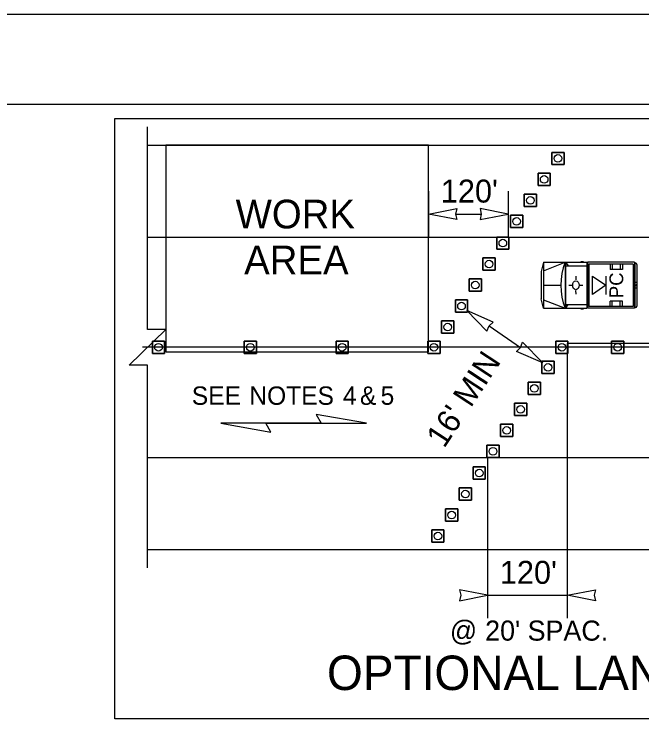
# Model space of a CAD drawing. Extents: x 99999.1 to 100095.7, y 99995 to 100010.7.
# Drawn here: x 100005.12 to 100007.305, y 100008.165 to 100010.687 of the extents above; entities that cross this region are included whole.
import ezdxf

# ---------------------------------------------------------------- set-up
doc = ezdxf.new("R2010")
doc.units = 0
for name, color, linetype in [('RD_ED_ShoulderPavedEdge', 7, 'Continuous'), ('RD_MK_LineEdgeWhite', 7, 'Continuous'), ('RD_MK_LineSkipCenter', 7, 'Continuous'), ('SH_DE_DetailHeading2Text', 7, 'Continuous'), ('SH_GI_PlotLimits', 7, 'Continuous'), ('SH_GI_SheetBorder', 7, 'Continuous'), ('SH_TI_Tables', 7, 'Continuous'), ('TR_WZ_MotoristVehicle', 7, 'Continuous'), ('TR_WZ_PortableSignMountBlk-Wht', 7, 'Continuous'), ('TR_WZ_TrafficCone', 7, 'Continuous'), ('TR_WZ_WorkAreaLabel', 7, 'Continuous'), ('TR_WZ_WorkZoneDetails', 7, 'Continuous'), ('TR_WZ_WorkZoneTextCurrent', 7, 'Continuous')]:
    doc.layers.add(name, color=color, linetype=linetype)

msp = doc.modelspace()

# ---------------------------------------------------------------- linework, layer by layer
at = {"layer": 'RD_ED_ShoulderPavedEdge'}
for p, q in [((100005.5832, 100010.2323), (100009.5005, 100010.2323)), ((100005.5832, 100008.8243), (100009.5005, 100008.8243))]:
    msp.add_line(p, q, dxfattribs=at)
at = {"layer": 'RD_MK_LineEdgeWhite'}
for p, q in [((100005.5832, 100009.9123), (100009.5005, 100009.9123)), ((100005.5832, 100009.1443), (100009.5005, 100009.1443))]:
    msp.add_line(p, q, dxfattribs=at)
at = {"layer": 'RD_MK_LineSkipCenter'}
msp.add_lwpolyline([(100009.484, 100009.5283), (100005.5667, 100009.5283)], dxfattribs=at)
at = {"layer": 'SH_GI_PlotLimits'}
msp.add_lwpolyline([(99999.0625, 99999.6875), (100016.0625, 99999.6875), (100016.0625, 100010.6875), (99999.0625, 100010.6875)], close=True, dxfattribs=at)
at = {"layer": 'SH_GI_SheetBorder'}
msp.add_line((100000, 100010.375), (100015.75, 100010.375), dxfattribs=at)
at = {"layer": 'SH_TI_Tables'}
msp.add_lwpolyline([(100005.4692, 100010.325), (100009.6146, 100010.325), (100009.6146, 100008.2343), (100005.4692, 100008.2343)], close=True, dxfattribs=at)
at = {"layer": 'TR_WZ_MotoristVehicle'}
for p, q in [((100006.9633, 100009.8243), (100006.9559, 100009.792)), ((100006.9633, 100009.8243), (100006.9633, 100009.6643)), ((100006.9633, 100009.8243), (100007.1144, 100009.8243)), ((100006.9633, 100009.795), (100007.0388, 100009.8243)), ((100007.0388, 100009.8243), (100007.0388, 100009.6643)), ((100007.0402, 100009.8243), (100007.0402, 100009.6643)), ((100007.0402, 100009.8243), (100007.0498, 100009.8119)), ((100007.0402, 100009.8119), (100007.1144, 100009.8119)), ((100007.0938, 100009.8266), (100007.1029, 100009.8266)), ((100007.1144, 100009.8243), (100007.1144, 100009.6643)), ((100007.2812, 100009.8243), (100007.1166, 100009.8243)), ((100007.1166, 100009.8243), (100007.1166, 100009.6643)), ((100007.2765, 100009.8179), (100007.1213, 100009.8179)), ((100007.1213, 100009.8179), (100007.1213, 100009.6707)), ((100007.1955, 100009.8179), (100007.1955, 100009.7995)), ((100007.2034, 100009.8179), (100007.2034, 100009.7995)), ((100007.2306, 100009.8179), (100007.2306, 100009.7995)), ((100007.2394, 100009.8179), (100007.2394, 100009.7995)), ((100007.2765, 100009.8179), (100007.2765, 100009.6707)), ((100007.2812, 100009.8243), (100007.2812, 100009.6643)), ((100007.2853, 100009.8217), (100007.2817, 100009.8217)), ((100007.2817, 100009.8217), (100007.2817, 100009.667)), ((100007.2889, 100009.8168), (100007.2889, 100009.6718)), ((100006.9559, 100009.792), (100006.9559, 100009.6966)), ((100007.2394, 100009.7995), (100007.1955, 100009.7995)), ((100007.0765, 100009.776), (100007.0765, 100009.7631)), ((100006.9633, 100009.7443), (100007.024, 100009.7443)), ((100007.0524, 100009.7444), (100007.0624, 100009.7444)), ((100007.0877, 100009.7441), (100007.0877, 100009.7441)), ((100007.1012, 100009.7437), (100007.0893, 100009.744)), ((100007.2889, 100009.7556), (100007.2817, 100009.7526)), ((100007.2889, 100009.7331), (100007.2817, 100009.7361)), ((100007.2869, 100009.7443), (100007.2837, 100009.7443)), ((100007.2853, 100009.7466), (100007.2853, 100009.7421)), ((100007.077, 100009.7136), (100007.0768, 100009.7256)), ((100006.9633, 100009.6643), (100006.9559, 100009.6966)), ((100006.9633, 100009.6936), (100007.0388, 100009.6643)), ((100007.1955, 100009.6707), (100007.1955, 100009.6891)), ((100007.2394, 100009.6891), (100007.1955, 100009.6891)), ((100007.2034, 100009.6707), (100007.2034, 100009.6891)), ((100007.2306, 100009.6707), (100007.2306, 100009.6891)), ((100007.2394, 100009.6707), (100007.2394, 100009.6891)), ((100006.9633, 100009.6643), (100007.1144, 100009.6643)), ((100007.0402, 100009.6767), (100007.1144, 100009.6767)), ((100007.0482, 100009.6767), (100007.0402, 100009.6643)), ((100007.0938, 100009.6621), (100007.1029, 100009.6621)), ((100007.2812, 100009.6643), (100007.1166, 100009.6643)), ((100007.2765, 100009.6707), (100007.1213, 100009.6707)), ((100007.2853, 100009.667), (100007.2817, 100009.667))]:
    msp.add_line(p, q, dxfattribs=at)
for centre, major_axis, start_param, end_param in [((100007.1468, 100009.7443), (0, -0.1679), 4.215667, 5.208926), ((100007.2853, 100009.8168), (0, 0.00488), 4.712389, 6.283185), ((100007.2853, 100009.6718), (0, -0.00488), 0, 1.570796)]:
    msp.add_ellipse(centre, major_axis=major_axis, ratio=0.73155, start_param=start_param, end_param=end_param, dxfattribs=at)
for centre, major_axis in [((100007.0765, 100009.7443), (0, 0.0154)), ((100007.2853, 100009.7443), (0, 0.00225))]:
    msp.add_ellipse(centre, major_axis=major_axis, ratio=0.73155, dxfattribs=at)
at = {"layer": 'TR_WZ_PortableSignMountBlk-Wht'}
msp.add_line((100007.1803, 100009.7763), (100007.1803, 100009.7123), dxfattribs=at)
msp.add_lwpolyline([(100007.1803, 100009.7443), (100007.1344, 100009.7123), (100007.1344, 100009.7763)], close=True, dxfattribs=at)
at = {"layer": 'TR_WZ_TrafficCone'}
for points in [[(100006.9925, 100010.2073), (100007.0352, 100010.2073), (100007.0352, 100010.1646), (100006.9925, 100010.1646), (100006.9925, 100010.2073)], [(100006.9925, 100010.1646), (100007.0352, 100010.1646), (100007.0352, 100010.2073), (100006.9925, 100010.2073), (100006.9925, 100010.1646)], [(100006.9445, 100010.1342), (100006.9872, 100010.1342), (100006.9872, 100010.0915), (100006.9445, 100010.0915), (100006.9445, 100010.1342)], [(100006.9445, 100010.0915), (100006.9872, 100010.0915), (100006.9872, 100010.1342), (100006.9445, 100010.1342), (100006.9445, 100010.0915)], [(100006.8965, 100010.0611), (100006.9392, 100010.0611), (100006.9392, 100010.0185), (100006.8965, 100010.0185), (100006.8965, 100010.0611)], [(100006.8965, 100010.0185), (100006.9392, 100010.0185), (100006.9392, 100010.0611), (100006.8965, 100010.0611), (100006.8965, 100010.0185)], [(100006.8485, 100009.9881), (100006.8912, 100009.9881), (100006.8912, 100009.9454), (100006.8485, 100009.9454), (100006.8485, 100009.9881)], [(100006.8485, 100009.9454), (100006.8912, 100009.9454), (100006.8912, 100009.9881), (100006.8485, 100009.9881), (100006.8485, 100009.9454)], [(100006.8432, 100009.9123), (100006.8005, 100009.9123), (100006.8005, 100009.8697), (100006.8432, 100009.8697), (100006.8432, 100009.9123)], [(100006.8432, 100009.8697), (100006.8005, 100009.8697), (100006.8005, 100009.9123), (100006.8432, 100009.9123), (100006.8432, 100009.8697)], [(100006.7952, 100009.8393), (100006.7525, 100009.8393), (100006.7525, 100009.7966), (100006.7952, 100009.7966), (100006.7952, 100009.8393)], [(100006.7952, 100009.7966), (100006.7525, 100009.7966), (100006.7525, 100009.8393), (100006.7952, 100009.8393), (100006.7952, 100009.7966)], [(100006.7472, 100009.7662), (100006.7045, 100009.7662), (100006.7045, 100009.7235), (100006.7472, 100009.7235), (100006.7472, 100009.7662)], [(100006.7472, 100009.7235), (100006.7045, 100009.7235), (100006.7045, 100009.7662), (100006.7472, 100009.7662), (100006.7472, 100009.7235)], [(100006.6992, 100009.6931), (100006.6565, 100009.6931), (100006.6565, 100009.6505), (100006.6992, 100009.6505), (100006.6992, 100009.6931)], [(100006.6992, 100009.6505), (100006.6565, 100009.6505), (100006.6565, 100009.6931), (100006.6992, 100009.6931), (100006.6992, 100009.6505)], [(100006.6512, 100009.6201), (100006.6085, 100009.6201), (100006.6085, 100009.5774), (100006.6512, 100009.5774), (100006.6512, 100009.6201)], [(100006.6512, 100009.5774), (100006.6085, 100009.5774), (100006.6085, 100009.6201), (100006.6512, 100009.6201), (100006.6512, 100009.5774)], [(100005.6005, 100009.5497), (100005.6432, 100009.5497), (100005.6432, 100009.507), (100005.6005, 100009.507), (100005.6005, 100009.5497)], [(100005.6005, 100009.507), (100005.6432, 100009.507), (100005.6432, 100009.5497), (100005.6005, 100009.5497), (100005.6005, 100009.507)], [(100005.9205, 100009.5497), (100005.9632, 100009.5497), (100005.9632, 100009.507), (100005.9205, 100009.507), (100005.9205, 100009.5497)], [(100005.9205, 100009.507), (100005.9632, 100009.507), (100005.9632, 100009.5497), (100005.9205, 100009.5497), (100005.9205, 100009.507)], [(100006.2405, 100009.5497), (100006.2832, 100009.5497), (100006.2832, 100009.507), (100006.2405, 100009.507), (100006.2405, 100009.5497)], [(100006.2405, 100009.507), (100006.2832, 100009.507), (100006.2832, 100009.5497), (100006.2405, 100009.5497), (100006.2405, 100009.507)], [(100006.6032, 100009.5497), (100006.5605, 100009.5497), (100006.5605, 100009.507), (100006.6032, 100009.507), (100006.6032, 100009.5497)], [(100006.6032, 100009.507), (100006.5605, 100009.507), (100006.5605, 100009.5497), (100006.6032, 100009.5497), (100006.6032, 100009.507)], [(100007.0488, 100009.5497), (100007.0061, 100009.5497), (100007.0061, 100009.507), (100007.0488, 100009.507), (100007.0488, 100009.5497)], [(100007.0488, 100009.507), (100007.0061, 100009.507), (100007.0061, 100009.5497), (100007.0488, 100009.5497), (100007.0488, 100009.507)], [(100007.2005, 100009.5497), (100007.2432, 100009.5497), (100007.2432, 100009.507), (100007.2005, 100009.507), (100007.2005, 100009.5497)], [(100007.2005, 100009.507), (100007.2432, 100009.507), (100007.2432, 100009.5497), (100007.2005, 100009.5497), (100007.2005, 100009.507)], [(100006.9582, 100009.4366), (100007.0009, 100009.4366), (100007.0009, 100009.4793), (100006.9582, 100009.4793), (100006.9582, 100009.4366)], [(100006.9582, 100009.4793), (100007.0009, 100009.4793), (100007.0009, 100009.4366), (100006.9582, 100009.4366), (100006.9582, 100009.4793)], [(100006.9102, 100009.3635), (100006.9529, 100009.3635), (100006.9529, 100009.4062), (100006.9102, 100009.4062), (100006.9102, 100009.3635)], [(100006.9102, 100009.4062), (100006.9529, 100009.4062), (100006.9529, 100009.3635), (100006.9102, 100009.3635), (100006.9102, 100009.4062)], [(100006.8622, 100009.2905), (100006.9049, 100009.2905), (100006.9049, 100009.3331), (100006.8622, 100009.3331), (100006.8622, 100009.2905)], [(100006.8622, 100009.3331), (100006.9049, 100009.3331), (100006.9049, 100009.2905), (100006.8622, 100009.2905), (100006.8622, 100009.3331)], [(100006.8142, 100009.2174), (100006.8569, 100009.2174), (100006.8569, 100009.2601), (100006.8142, 100009.2601), (100006.8142, 100009.2174)], [(100006.8142, 100009.2601), (100006.8569, 100009.2601), (100006.8569, 100009.2174), (100006.8142, 100009.2174), (100006.8142, 100009.2601)], [(100006.7662, 100009.1443), (100006.8089, 100009.1443), (100006.8089, 100009.187), (100006.7662, 100009.187), (100006.7662, 100009.1443)], [(100006.7662, 100009.187), (100006.8089, 100009.187), (100006.8089, 100009.1443), (100006.7662, 100009.1443), (100006.7662, 100009.187)], [(100006.7182, 100009.1113), (100006.7608, 100009.1113), (100006.7608, 100009.0686), (100006.7182, 100009.0686), (100006.7182, 100009.1113)], [(100006.7182, 100009.0686), (100006.7608, 100009.0686), (100006.7608, 100009.1113), (100006.7182, 100009.1113), (100006.7182, 100009.0686)], [(100006.6702, 100009.0382), (100006.7128, 100009.0382), (100006.7128, 100008.9955), (100006.6702, 100008.9955), (100006.6702, 100009.0382)], [(100006.6702, 100008.9955), (100006.7128, 100008.9955), (100006.7128, 100009.0382), (100006.6702, 100009.0382), (100006.6702, 100008.9955)], [(100006.6222, 100008.9651), (100006.6648, 100008.9651), (100006.6648, 100008.9225), (100006.6222, 100008.9225), (100006.6222, 100008.9651)], [(100006.6222, 100008.9225), (100006.6648, 100008.9225), (100006.6648, 100008.9651), (100006.6222, 100008.9651), (100006.6222, 100008.9225)], [(100006.5742, 100008.8921), (100006.6168, 100008.8921), (100006.6168, 100008.8494), (100006.5742, 100008.8494), (100006.5742, 100008.8921)], [(100006.5742, 100008.8494), (100006.6168, 100008.8494), (100006.6168, 100008.8921), (100006.5742, 100008.8921), (100006.5742, 100008.8494)]]:
    msp.add_lwpolyline(points, dxfattribs=at)
for centre in [(100007.0139, 100010.1859), (100006.9659, 100010.1129), (100006.9179, 100010.0398), (100006.8699, 100009.9667), (100006.8218, 100009.891), (100006.7738, 100009.8179), (100006.7258, 100009.7449), (100006.6778, 100009.6718), (100006.6298, 100009.5987), (100005.6219, 100009.5283), (100005.9419, 100009.5283), (100006.2619, 100009.5283), (100006.5818, 100009.5283), (100007.0275, 100009.5283), (100007.2219, 100009.5283), (100006.9795, 100009.4579), (100006.9315, 100009.3849), (100006.8835, 100009.3118), (100006.8355, 100009.2387), (100006.7875, 100009.1657), (100006.7395, 100009.0899), (100006.6915, 100009.0169), (100006.6435, 100008.9438), (100006.5955, 100008.8707)]:
    msp.add_circle(centre, 0.0133, dxfattribs=at)
at = {"layer": 'TR_WZ_WorkZoneDetails'}
for p, q in [((100006.5632, 100010.0723), (100006.5632, 100009.9123)), ((100006.8405, 100010.0723), (100006.8405, 100009.9123)), ((100006.6569, 100009.9923), (100006.7468, 100009.9923)), ((100006.7738, 100009.6027), (100006.8836, 100009.5271)), ((100005.9961, 100009.2638), (100006.189, 100009.2638)), ((100006.189, 100009.2638), (100005.9961, 100009.2638)), ((100006.7688, 100009.1443), (100006.7688, 100008.5843)), ((100007.0462, 100008.8243), (100007.0462, 100008.5843)), ((100006.7688, 100008.6643), (100007.0462, 100008.6643))]:
    msp.add_line(p, q, dxfattribs=at)
msp.add_lwpolyline([(100005.5832, 100008.7603), (100005.5832, 100009.4664), (100005.5192, 100009.4664), (100005.6472, 100009.5903), (100005.5832, 100009.5903), (100005.5832, 100010.2963)], dxfattribs=at)
for points in [[(100005.6472, 100010.2323), (100005.6472, 100009.5123), (100006.5632, 100009.5123), (100006.5632, 100010.2323)], [(100006.5632, 100009.9923), (100006.6615, 100010.0116), (100006.6569, 100009.9923), (100006.6615, 100009.9731)], [(100006.8405, 100009.9923), (100006.7423, 100010.0116), (100006.7468, 100009.9923), (100006.7423, 100009.9731)], [(100006.6965, 100009.6558), (100006.7666, 100009.5842), (100006.7738, 100009.6027), (100006.7884, 100009.616)], [(100006.9608, 100009.4739), (100006.869, 100009.5138), (100006.8836, 100009.5271), (100006.8908, 100009.5455)], [(100007.0462, 100009.5417), (100007.0462, 100008.8243), (100008.0246, 100008.8243), (100008.0246, 100009.5417)], [(100006.3462, 100009.2638), (100006.1711, 100009.2946), (100006.189, 100009.2638)], [(100005.8389, 100009.2638), (100006.0139, 100009.2329), (100005.9961, 100009.2638)], [(100006.7688, 100008.6643), (100006.6706, 100008.6836), (100006.6751, 100008.6643), (100006.6706, 100008.6451)], [(100007.0462, 100008.6643), (100007.1445, 100008.6836), (100007.1399, 100008.6643), (100007.1445, 100008.6451)]]:
    msp.add_lwpolyline(points, close=True, dxfattribs=at)

# ---------------------------------------------------------------- texts
at = {"layer": 'SH_DE_DetailHeading2Text'}
msp.add_text('OPTIONAL LANE SHIFT DETAIL', height=0.12, rotation=360, dxfattribs=at).set_placement((100006.209, 100008.3343))
at = {"layer": 'TR_WZ_MotoristVehicle'}
msp.add_text('PC', height=0.048, rotation=90, dxfattribs=at).set_placement((100007.2414, 100009.6995))
at = {"layer": 'TR_WZ_WorkAreaLabel'}
for s, p in [('WORK', (100005.8907, 100009.9423)), ('AREA', (100005.9203, 100009.7823))]:
    msp.add_text(s, height=0.1, dxfattribs=at).set_placement(p)
at = {"layer": 'TR_WZ_WorkZoneTextCurrent'}
for s, height, rotation, p in [("120'", 0.08, 360, (100006.6057, 100010.0323)), ("16' MIN", 0.08, 56.6977, (100006.6173, 100009.1738)), ("120'", 0.08, 360, (100006.8114, 100008.7043)), ('@', 0.07, 360, (100006.6373, 100008.5063)), ("20' SPAC.", 0.07, 360, (100006.7602, 100008.5063))]:
    msp.add_text(s, height=height, rotation=rotation, dxfattribs=at).set_placement(p)
for s, p in [('SEE', (100005.738, 100009.3278)), ('NOTES', (100005.9385, 100009.3278)), ('4', (100006.2645, 100009.3278)), ('&', (100006.324, 100009.3278)), ('5', (100006.3959, 100009.3278))]:
    msp.add_text(s, height=0.064, dxfattribs=at).set_placement(p)

doc.saveas('drawing.dxf')
